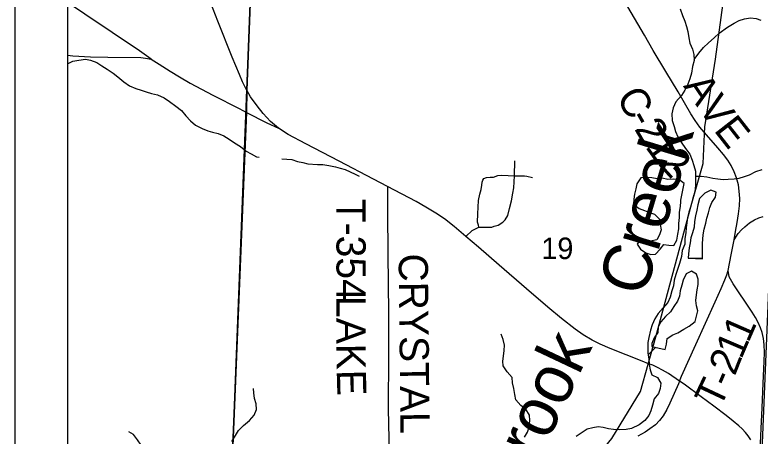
# Model space of a CAD drawing. Extents: x 0 to 34, y 0 to 22.
# Drawn here: x 2.735 to 4.185, y 17.152 to 17.972 of the extents above; entities that cross this region are included whole.
import ezdxf

# ---------------------------------------------------------------- set-up
doc = ezdxf.new("R2010")
doc.units = 0
for name, color, linetype in [('GM_X_Corporation', 7, 'Continuous'), ('GM_X_County_Road', 7, 'Continuous'), ('GM_X_County_Road_Text', 7, 'Continuous'), ('GM_X_Minor_Lake', 7, 'Continuous'), ('GM_X_Minor_River', 7, 'Continuous'), ('GM_X_Minor_River_Text', 7, 'Continuous'), ('GM_X_Rail_Line', 7, 'Continuous'), ('GM_X_Section_Text', 7, 'Continuous'), ('GM_X_State_Route', 7, 'Continuous'), ('GM_X_Township_Road', 7, 'Continuous'), ('GM_X_Township_Road_Text', 7, 'Continuous'), ('SH_Data', 7, 'Continuous')]:
    doc.layers.add(name, color=color, linetype=linetype)

msp = doc.modelspace()

# ---------------------------------------------------------------- linework, layer by layer
at = {"layer": 'GM_X_Corporation'}
for points in [[(7.1023, 20.9204), (2.837, 20.9204), (2.837, 14.1204), (9.637, 14.1204), (9.637, 20.9204), (9.4036, 20.9204), (9.4022, 20.8667), (9.2273, 20.8723), (9.1354, 20.8749), (9.124, 20.8753), (8.9858, 20.878), (8.9676, 20.8785), (8.8663, 20.881), (8.6259, 20.8892), (8.5535, 20.8914), (8.5421, 20.8915), (8.4667, 20.8934), (8.0602, 20.9055), (7.9522, 20.9084), (7.1104, 20.9188)], [(3.3169, 20.9204), (2.837, 20.9204), (2.837, 14.9888), (3.0725, 14.9816), (3.0874, 15.351), (3.0879, 15.3623), (3.0883, 15.3712), (3.1072, 15.7483), (3.1177, 16.2414), (3.14, 16.6736), (3.1852, 17.7826), (3.1864, 17.8248), (3.233, 19.0394), (3.2586, 19.6098), (3.2623, 19.6596), (3.2721, 19.8755), (3.2728, 19.892), (3.2744, 19.9301), (3.2774, 20.0014), (3.2794, 20.0412), (3.3026, 20.5526), (3.3089, 20.7046), (3.3168, 20.9187)], [(2.837, 18.0425), (2.837, 17.0399), (3.155, 17.0299), (3.1939, 18.0257)], [(3.1939, 18.0257), (4.2238, 17.9879), (4.1823, 16.9818), (3.1533, 17.0117), (3.155, 17.0299)]]:
    msp.add_lwpolyline(points, close=True, dxfattribs=at)
msp.add_lwpolyline([(3.233, 19.0394), (3.1864, 17.8248), (3.1852, 17.7826), (3.14, 16.6736), (3.1177, 16.2414), (3.1072, 15.7483)], dxfattribs=at)
at = {"layer": 'GM_X_County_Road'}
for points in [[(4.134, 17.5342), (4.1368, 17.5502), (4.1398, 17.5676), (4.1424, 17.5846), (4.1445, 17.6001), (4.1449, 17.6148), (4.1441, 17.6289), (4.1424, 17.6412), (4.1387, 17.6548), (4.1343, 17.6665), (4.1285, 17.6786), (4.1219, 17.6892), (4.1134, 17.7002), (4.1023, 17.7131), (4.0803, 17.7382), (4.0673, 17.7536), (4.0582, 17.7661), (4.0498, 17.7795), (4.025, 17.822), (4.0013, 17.8617), (3.9768, 17.9027), (3.9595, 17.9322), (3.9402, 17.9653), (3.9208, 17.9981)], [(4.1222, 17.4744), (4.1286, 17.5048), (4.134, 17.5342)], [(4.1822, 17.1107), (4.185, 17.1244), (4.187, 17.1674), (4.1889, 17.2076), (4.1909, 17.2557), (4.1925, 17.2974), (4.1929, 17.3158), (4.1924, 17.3302), (4.1911, 17.3422), (4.1884, 17.3542), (4.1856, 17.3629), (4.1811, 17.3732), (4.1755, 17.3833), (4.169, 17.3936), (4.16, 17.4071), (4.1385, 17.4387), (4.132, 17.4487), (4.1243, 17.4624), (4.1222, 17.4744)]]:
    msp.add_lwpolyline(points, dxfattribs=at)
at = {"layer": 'GM_X_Minor_Lake'}
for points in [[(4.0372, 17.6436), (4.0262, 17.6515), (4.0152, 17.6522), (4.0054, 17.6518), (3.9943, 17.6544), (3.9841, 17.6529), (3.9739, 17.6547), (3.9644, 17.6551), (3.9523, 17.6546), (3.9451, 17.6432), (3.9429, 17.6333), (3.9403, 17.6227), (3.9388, 17.6132), (3.9381, 17.6037), (3.9491, 17.595), (3.9598, 17.5913), (3.9696, 17.5875), (3.9795, 17.5841), (3.9894, 17.5735), (3.9902, 17.5637), (3.9922, 17.5534), (3.9888, 17.5439), (3.9835, 17.534), (3.9714, 17.5313), (3.9619, 17.5332), (3.9517, 17.5351), (3.9457, 17.5255), (3.9521, 17.5157), (3.9624, 17.5089), (3.9719, 17.5055), (3.9814, 17.5063), (3.9904, 17.5158), (3.9976, 17.5254), (4.0071, 17.5235), (4.0166, 17.5231), (4.0226, 17.5338), (4.0244, 17.5452), (4.0263, 17.5554), (4.0266, 17.5657), (4.0277, 17.5775), (4.028, 17.5877), (4.0299, 17.5991), (4.0302, 17.6086), (4.0306, 17.6113)], [(4.0306, 17.6113), (4.0372, 17.6436)], [(4.0728, 17.4975), (4.0727, 17.5169), (4.0723, 17.5271), (4.0737, 17.5439), (4.0756, 17.5549), (4.0793, 17.5663), (4.0812, 17.5761), (4.0845, 17.5868), (4.0871, 17.5971), (4.0905, 17.6066), (4.098, 17.6172), (4.0991, 17.6271), (4.0889, 17.6305), (4.0771, 17.6251), (4.067, 17.6144), (4.0632, 17.6023), (4.0614, 17.592), (4.0588, 17.5806), (4.0573, 17.57), (4.0566, 17.5586), (4.0532, 17.548), (4.0499, 17.5381), (4.0484, 17.5286), (4.0465, 17.5187), (4.0451, 17.5069), (4.0444, 17.4986)], [(4.0444, 17.4986), (4.0728, 17.4975)], [(4.0728, 17.4978), (4.0444, 17.4986)], [(4.0001, 17.3211), (4.0023, 17.331), (4.0038, 17.342), (4.0147, 17.3493), (4.0246, 17.3531), (4.0363, 17.3607), (4.0465, 17.3665), (4.0586, 17.3756), (4.0608, 17.3859), (4.0634, 17.3958), (4.0607, 17.4056), (4.0599, 17.4159), (4.0606, 17.4269), (4.0625, 17.4371), (4.0643, 17.447), (4.0639, 17.4576), (4.0608, 17.4675), (4.0509, 17.4732), (4.0411, 17.4678), (4.0351, 17.4556), (4.0321, 17.4458), (4.0291, 17.4351), (4.028, 17.4245), (4.0239, 17.415), (4.0171, 17.4043), (4.0103, 17.3944), (4.0005, 17.3853), (3.9918, 17.375), (3.9866, 17.3647), (3.9855, 17.3541), (3.9787, 17.3438), (3.9742, 17.3324), (3.9739, 17.3267)], [(3.9739, 17.3267), (4.0001, 17.3211)]]:
    msp.add_lwpolyline(points, dxfattribs=at)
at = {"layer": 'GM_X_Minor_River'}
for points in [[(4.0288, 17.9833), (4.0338, 17.9704), (4.0384, 17.9594), (4.0415, 17.9492), (4.0442, 17.9393), (4.0458, 17.9268), (4.0477, 17.9165), (4.0531, 17.9048), (4.0554, 17.8949)], [(4.0554, 17.8949), (4.0566, 17.8851), (4.0653, 17.8969), (4.0743, 17.9083), (4.0845, 17.9174), (4.0955, 17.927), (4.1053, 17.9361), (4.1215, 17.9476), (4.134, 17.9556), (4.1442, 17.9609), (4.1544, 17.964), (4.1658, 17.9656), (4.1768, 17.9648), (4.1863, 17.9615)], [(4.0554, 17.8949), (4.0562, 17.8832), (4.0529, 17.871), (4.0514, 17.8585), (4.0481, 17.8471), (4.0439, 17.8372), (4.0383, 17.825), (4.0319, 17.8151), (4.021, 17.8026), (4.0157, 17.7911), (4.0127, 17.779), (4.0135, 17.7665), (4.0174, 17.7547), (4.0201, 17.7449), (4.0247, 17.7342), (4.0312, 17.7244), (4.0396, 17.7115), (4.048, 17.7005), (4.0526, 17.6888), (4.0557, 17.6785), (4.0591, 17.6676), (4.0592, 17.6421), (4.0582, 17.6322), (4.0555, 17.622), (4.0533, 17.6125), (4.0496, 17.5999), (4.0462, 17.5878), (4.0436, 17.5771), (4.0407, 17.5582), (4.0403, 17.5479), (4.0381, 17.5369), (4.0382, 17.5259), (4.0333, 17.5133), (4.0315, 17.5019), (4.0277, 17.4883), (4.0206, 17.4666), (4.0176, 17.456), (4.0162, 17.4446), (4.0132, 17.4347), (4.0098, 17.4225), (4.0049, 17.4126), (3.9963, 17.402), (3.9861, 17.3906), (3.9797, 17.3803), (3.9748, 17.3689), (3.9714, 17.3586), (3.9681, 17.3442), (3.9659, 17.3343), (3.9663, 17.3233), (3.966, 17.3138), (3.9683, 17.3024), (3.9691, 17.2914), (3.971, 17.2815), (3.9741, 17.2713), (3.9848, 17.2664), (3.9913, 17.2554), (3.9902, 17.2452), (3.9868, 17.2353), (3.9785, 17.225), (3.9752, 17.2129), (3.9718, 17.2018), (3.968, 17.1923), (3.9605, 17.1828), (3.9492, 17.1744), (3.9344, 17.1675), (3.9242, 17.1652), (3.9117, 17.1648), (3.8995, 17.1655), (3.8897, 17.1666), (3.879, 17.1692), (3.8696, 17.1707), (3.859, 17.1688), (3.848, 17.1661), (3.8366, 17.1584), (3.8268, 17.1519)], [(2.837, 17.8766), (2.8474, 17.8817), (2.8592, 17.8833), (2.8721, 17.8856), (2.8819, 17.8837), (2.8941, 17.8792), (2.904, 17.8724), (2.9142, 17.866), (2.926, 17.8581), (2.9355, 17.8509), (2.947, 17.8415), (2.958, 17.8335), (2.9705, 17.8286), (2.9804, 17.8253), (2.9903, 17.8223), (3.0009, 17.8189), (3.0123, 17.8159), (3.0252, 17.8102), (3.0359, 17.8031), (3.0477, 17.7944), (3.0591, 17.7857), (3.0675, 17.7755), (3.0766, 17.7656), (3.0861, 17.7573), (3.0994, 17.7505), (3.1101, 17.7464), (3.1196, 17.7438), (3.1302, 17.7408), (3.1412, 17.7363), (3.1518, 17.7302), (3.1621, 17.7227), (3.1735, 17.7155), (3.1849, 17.7064), (3.1945, 17.7012), (3.2051, 17.6959), (3.21, 17.6951)], [(3.254, 17.6915), (3.2639, 17.6908), (3.2737, 17.6905), (3.2844, 17.6863), (3.295, 17.6845), (3.3045, 17.6822), (3.3235, 17.6808), (3.3337, 17.6808), (3.3455, 17.6789), (3.3584, 17.676), (3.3679, 17.6737), (3.3777, 17.6711), (3.3872, 17.6666), (3.3971, 17.6621), (3.4047, 17.6579)], [(4.0592, 17.6581), (4.0702, 17.6581), (4.0812, 17.657), (4.0926, 17.6544), (4.1024, 17.6525), (4.1127, 17.6518), (4.1225, 17.6522), (4.1339, 17.6526), (4.1437, 17.6542), (4.154, 17.6573), (4.1642, 17.6607), (4.1763, 17.6668), (4.1884, 17.6707)], [(3.726, 17.1504), (3.7323, 17.1603), (3.7353, 17.1702), (3.7364, 17.1827), (3.736, 17.1934), (3.7291, 17.2051), (3.7192, 17.2119), (3.7097, 17.2229), (3.7074, 17.2335), (3.7054, 17.2453), (3.7031, 17.2559), (3.7023, 17.2661), (3.6928, 17.2775), (3.6851, 17.2888), (3.6843, 17.2983), (3.6854, 17.3082), (3.6865, 17.3188), (3.6872, 17.3295), (3.6845, 17.3405), (3.6807, 17.3507)], [(3.9817, 17.3251), (3.9666, 17.3105)], [(3.1568, 17.1419), (3.164, 17.1533), (3.1696, 17.1632), (3.1795, 17.1731), (3.1915, 17.1826), (3.2002, 17.1929), (3.2051, 17.2039), (3.2043, 17.2149), (3.2008, 17.2255), (3.1996, 17.2369), (3.1988, 17.2453)], [(3.1002, 16.9374), (3.0997, 16.9629), (3.0966, 16.9723), (3.0939, 16.983), (3.0874, 16.9939), (3.0759, 17.0136), (3.0671, 17.0254), (3.0584, 17.0352), (3.0485, 17.0447), (3.0382, 17.0564), (3.0378, 17.0666), (3.0312, 17.0791), (3.024, 17.0897), (3.0129, 17.1011), (2.9989, 17.1143), (2.9897, 17.1249), (2.9806, 17.1351), (2.9737, 17.145), (2.9657, 17.1556), (2.9569, 17.1609)]]:
    msp.add_lwpolyline(points, dxfattribs=at)
at = {"layer": 'GM_X_Rail_Line'}
msp.add_lwpolyline([(3.3578, 16.4966), (3.4025, 16.5303), (3.4342, 16.5651), (3.4483, 16.5903), (3.4778, 16.7044), (3.4959, 16.7405), (3.5487, 16.7816), (3.602, 16.8153), (3.7034, 16.9055), (3.7667, 16.9815), (3.8459, 17.086), (3.8965, 17.1477), (3.952, 17.2395), (3.9821, 17.3456), (4.0518, 17.6053), (4.074, 17.6829), (4.0772, 17.7542), (4.0978, 17.8856), (4.1311, 18.1295)], dxfattribs=at)
at = {"layer": 'GM_X_State_Route'}
for points in [[(3.2475, 17.7514), (3.2323, 17.7645), (3.2182, 17.7796), (3.206, 17.7948), (3.1935, 17.8125), (3.1866, 17.8242), (3.1862, 17.8248), (3.178, 17.8414), (3.1718, 17.8554), (3.1579, 17.8893), (3.1296, 17.9592), (3.1068, 18.0185)], [(3.9677, 17.2933), (3.955, 17.2983), (3.893, 17.3229), (3.8736, 17.3313), (3.8577, 17.3391), (3.8407, 17.3492), (3.8248, 17.3602), (3.7981, 17.3814), (3.7718, 17.4033), (3.7304, 17.4387), (3.6769, 17.4849), (3.6367, 17.5196), (3.6122, 17.5408), (3.5895, 17.56), (3.5706, 17.5747), (3.5539, 17.5861), (3.5344, 17.5978), (3.5153, 17.6084), (3.4595, 17.6381), (3.4326, 17.6521), (3.3656, 17.687), (3.301, 17.7206), (3.2667, 17.7392), (3.2475, 17.7514)], [(4.0276, 17.2595), (4.0064, 17.274), (3.995, 17.2808), (3.9851, 17.2859), (3.9758, 17.2901), (3.9677, 17.2933)], [(4.1668, 17.1455), (4.1616, 17.153), (4.1562, 17.1597), (4.1498, 17.1665), (4.1433, 17.1724), (4.1323, 17.1818), (4.1183, 17.1927), (4.0946, 17.2109), (4.0702, 17.2291), (4.037, 17.2533), (4.0276, 17.2595)]]:
    msp.add_lwpolyline(points, dxfattribs=at)
at = {"layer": 'GM_X_Township_Road'}
for points in [[(3.0003, 17.8855), (2.9774, 17.9017), (2.8713, 17.9729), (2.837, 17.996)], [(2.837, 17.893), (2.8474, 17.8922), (2.8818, 17.8901), (2.9159, 17.8892), (2.9798, 17.8885), (2.9892, 17.8875), (3.0003, 17.8855), (3.0156, 17.876), (3.0368, 17.8625), (3.055, 17.851), (3.076, 17.8391), (3.1197, 17.8158), (3.1709, 17.7894), (3.1854, 17.7821)], [(3.1854, 17.7821), (3.2251, 17.762), (3.2475, 17.7514)], [(3.6122, 17.5408), (3.6242, 17.5525), (3.6373, 17.5585), (3.6444, 17.5589), (3.6563, 17.5589), (3.6627, 17.5589), (3.6675, 17.5607), (3.675, 17.563), (3.6843, 17.5686), (3.6888, 17.573), (3.694, 17.5813), (3.6974, 17.5951), (3.7008, 17.61), (3.7037, 17.625), (3.7056, 17.635), (3.7071, 17.6589), (3.7075, 17.6877)], [(3.6469, 17.6533), (3.6524, 17.6552), (3.6593, 17.6558), (3.6657, 17.6563), (3.6742, 17.659), (3.6821, 17.6597), (3.7071, 17.6589), (3.7261, 17.6586), (3.731, 17.6582), (3.7418, 17.6556)], [(3.6373, 17.5585), (3.6365, 17.563), (3.635, 17.5686), (3.6354, 17.5846), (3.6369, 17.6108), (3.6395, 17.6231), (3.6419, 17.6323), (3.6433, 17.6406), (3.644, 17.6466), (3.645, 17.6503), (3.6469, 17.6533)], [(3.4595, 17.6381), (3.4598, 17.5868), (3.4604, 17.5083), (3.4613, 17.4481), (3.4616, 17.3928), (3.4619, 17.339), (3.4618, 17.2848), (3.4612, 17.2315), (3.4611, 17.2077), (3.4618, 17.1743), (3.4628, 17.1238)], [(4.134, 17.5342), (4.1419, 17.5468), (4.1482, 17.5534), (4.155, 17.5593), (4.1641, 17.5669), (4.1734, 17.5731), (4.1819, 17.577), (4.1905, 17.5797)], [(4.1222, 17.4744), (4.1286, 17.5048), (4.134, 17.5342)], [(4.0276, 17.2595), (4.0317, 17.2692), (4.0595, 17.3304), (4.097, 17.4139), (4.1087, 17.4398), (4.1159, 17.4562), (4.1197, 17.4663), (4.1222, 17.4744)], [(4.0276, 17.2595), (4.0258, 17.2542), (4.0089, 17.2162), (4.0029, 17.2041), (3.9961, 17.1918), (3.989, 17.1825), (3.9809, 17.1743), (3.9704, 17.1663), (3.9609, 17.1599), (3.9467, 17.1521)]]:
    msp.add_lwpolyline(points, dxfattribs=at)
at = {"layer": 'SH_Data'}
msp.add_line((2.7349, 21.0001), (2.7349, 14.0001), dxfattribs=at)

# ---------------------------------------------------------------- texts
at = {"layer": 'GM_X_County_Road_Text'}
for s, rotation, p in [('A', 303.9507, (4.0343, 17.8333)), ('C', 299.6631, (3.9037, 17.8118)), ('V', 304.8241, (4.0627, 17.791)), ('-', 299.8341, (3.9269, 17.7711)), ('E', 308.0096, (4.0933, 17.7472)), ('2', 300.6595, (3.939, 17.7501)), ('1', 305.8588, (3.9599, 17.7153)), ('2', 312.1026, (3.9847, 17.6816))]:
    msp.add_text(s, height=0.0568, rotation=rotation, dxfattribs=at).set_placement(p)
at = {"layer": 'GM_X_Minor_River_Text'}
for s, rotation, p in [('Creek', 73.2469, (3.9591, 17.4206)), ('Mudbrook', 64.7213, (3.6184, 16.8168))]:
    msp.add_text(s, height=0.09473, rotation=rotation, dxfattribs=at).set_placement(p)
at = {"layer": 'GM_X_Section_Text'}
msp.add_text('19', height=0.04186, rotation=0, dxfattribs=at).set_placement((3.7591, 17.4967))
at = {"layer": 'GM_X_Township_Road_Text'}
for s, height, rotation, p in [('T-354', 0.05682, 270, (3.3605, 17.6141)), ('CRYSTAL', 0.05682, 270.5954, (3.4814, 17.5073)), ('L', 0.0568, 270.0043, (3.3604, 17.425)), ('A', 0.0568, 270.0825, (3.3604, 17.3824)), ('1', 0.0568, 66.5083, (4.1619, 17.3324)), ('1', 0.0568, 66.7741, (4.1481, 17.3003)), ('K', 0.0568, 270.4599, (3.3604, 17.332)), ('2', 0.0568, 68.5377, (4.1355, 17.2681)), ('E', 0.0568, 271.5681, (3.3609, 17.2808)), ('T', 0.0568, 64.8016, (4.1066, 17.2045)), ('-', 0.0568, 66.6926, (4.1255, 17.2448))]:
    msp.add_text(s, height=height, rotation=rotation, dxfattribs=at).set_placement(p)

doc.saveas('drawing.dxf')
